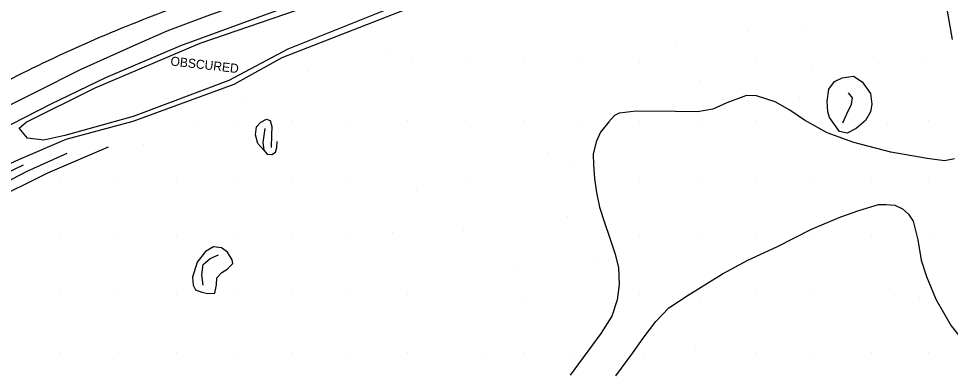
# Model space of a CAD drawing. Extents: x 524772 to 528246, y 273285 to 283088.
# Drawn here: x 526707.5 to 526864.4, y 277185.1 to 277244.2 of the extents above; entities that cross this region are included whole.
import ezdxf

# ---------------------------------------------------------------- set-up
doc = ezdxf.new("R2010")
doc.units = 0
for name, color, linetype in [('Exist Roads EOP', 7, 'Continuous'), ('PH Exist DTM Breakline', 7, 'Continuous'), ('PH Exist DTM Obscure Area', 7, 'Continuous'), ('PH Exist DTM Obscure Area Text', 7, 'Continuous'), ('PH Exist DTM Point', 7, 'Continuous')]:
    doc.layers.add(name, color=color, linetype=linetype)

msp = doc.modelspace()

# ---------------------------------------------------------------- linework, layer by layer
at = {"layer": 'Exist Roads EOP'}
for points in [[(526525.38, 277117.18), (526537.47, 277126.58), (526549.67, 277136.03), (526561.66, 277145.86), (526573.73, 277155.58), (526585.94, 277165.37), (526597.96, 277175.18), (526610, 277184.81), (526621.9, 277194.28), (526634.13, 277203.58), (526646.08, 277212.63), (526658.24, 277222.04), (526669.92, 277231.55), (526680.97, 277240.89), (526692.26, 277251.07), (526703.26, 277261.58), (526714.12, 277272.6), (526724.89, 277283.84)], [(526530.1, 277111.56), (526542.2, 277120.68), (526554.48, 277129.66), (526567.27, 277138.8), (526580.03, 277147.94), (526592.95, 277157.04), (526605.22, 277166), (526617.99, 277175.14), (526630.31, 277183.84), (526642.39, 277192.47), (526654.84, 277201.42), (526667.47, 277210.57), (526680.56, 277219.44), (526693.6, 277227.28), (526707.3, 277234.6), (526721.28, 277241.1), (526735.33, 277246.63), (526749.05, 277251.37), (526763.33, 277255.46)]]:
    msp.add_spline(points, degree=3, dxfattribs=at)
at = {"layer": 'PH Exist DTM Breakline'}
for points in [[(526763.16, 277254.94), (526770.89, 277255.73), (526781.75, 277257.24), (526792.41, 277258.33), (526805.01, 277259.77), (526814.77, 277261.06), (526820.49, 277262.09), (526831.77, 277264.5), (526839.43, 277266.1), (526844.64, 277267.15), (526846.81, 277267.46), (526848.71, 277267.21), (526850.47, 277266.69), (526852.49, 277265.75), (526854.47, 277264.73), (526856.33, 277263.31), (526858.04, 277261.63), (526859.43, 277260.28), (526861.08, 277258.13), (526862.05, 277255.93), (526863.07, 277250.3), (526864.72, 277240.67)], [(526847.95, 277264.75), (526844.32, 277264.46), (526838.89, 277263.84), (526832.99, 277262.77), (526819.99, 277260.54), (526807.41, 277258.41), (526799.95, 277257.02), (526790.72, 277255.24), (526777.17, 277252.42), (526771.43, 277250.94), (526751.2, 277245.63), (526734.74, 277239.62), (526722.1, 277234.23), (526712.9, 277229.79), (526692.94, 277219.54), (526680.47, 277212.08), (526671.94, 277206.38)], [(526668.44, 277207.44), (526674.33, 277211.13), (526682.73, 277216.49), (526694.76, 277223.83), (526701.36, 277227.29), (526710.42, 277231.84), (526718, 277235.67), (526727.3, 277239.84), (526732.51, 277242.1), (526739.25, 277244.63), (526749.19, 277248.25), (526758.54, 277251.05), (526765.41, 277252.59), (526775.09, 277254.44), (526784.56, 277255.93)], [(526789.24, 277250.35), (526781.49, 277248.42), (526774.73, 277246.51), (526751.8, 277237.58), (526743.72, 277233.09), (526726.74, 277226.86), (526715.41, 277223.85), (526707.44, 277220.38), (526700.02, 277217.03), (526690.01, 277212.14), (526686.82, 277210.4), (526682.59, 277208.58)], [(526845.76, 277225.15), (526844.09, 277227.52), (526843.81, 277228.48), (526843.66, 277230.28), (526843.93, 277232.32), (526844.93, 277233.61), (526846.2, 277234.21), (526848.11, 277234.47), (526849.57, 277233.56), (526850.95, 277231.57), (526851.2, 277229.8), (526850.97, 277228.46), (526850.12, 277227.01), (526848.54, 277225.69), (526847.02, 277224.91), (526845.76, 277225.15)], [(526865.13, 277220.56), (526863.41, 277220.24), (526860.54, 277220.61), (526854.39, 277221.7), (526848.17, 277223.32), (526843.66, 277224.97), (526839.83, 277227.11), (526837.39, 277228.78), (526834.9, 277230.19), (526831.77, 277231.19), (526830.07, 277231.24), (526826.75, 277230.03), (526824.39, 277228.93), (526821.83, 277228.47), (526818.1, 277228.55), (526811.48, 277228.58), (526808.66, 277228.29), (526807.86, 277227.87), (526806.9, 277226.78), (526805.51, 277225.09), (526804.75, 277223.45), (526804.23, 277221.34), (526804.31, 277219.56), (526804.48, 277217.28), (526804.82, 277214.9), (526805.34, 277212.43), (526806.24, 277209.7), (526806.98, 277207.37), (526807.91, 277204.67), (526808.5, 277202.3), (526808.63, 277199.41), (526808.28, 277196.85), (526807.39, 277194.1), (526805.57, 277191.17), (526800.36, 277184.16)], [(526846.3, 277226.64), (526847.21, 277228.67), (526847.76, 277229.72), (526847.94, 277230.87), (526847.25, 277231.7)], [(526748.96, 277225.69), (526748.63, 277223.3), (526748.76, 277222.01), (526747.79, 277223.18), (526747.35, 277224.63), (526747.52, 277225.96), (526748.26, 277226.73), (526749.21, 277227.26), (526749.83, 277227.01), (526750.15, 277226.04), (526750.09, 277224.61), (526750.03, 277222.46)], [(526748.76, 277222.01), (526749.33, 277221.37), (526750.15, 277221.29), (526750.76, 277221.71), (526750.95, 277222.51), (526751.05, 277223.49)], [(526666.98, 277193.82), (526672.99, 277197.85), (526680.2, 277202), (526686, 277205.39), (526689.44, 277207.33), (526692.18, 277209.1), (526694.86, 277210.75), (526697.53, 277212.3), (526700.33, 277213.76), (526703.33, 277215.46), (526706.45, 277217.2), (526708.93, 277218.52), (526712.27, 277220), (526715.64, 277221.54)], [(526722.58, 277222.53), (526712.35, 277218.16), (526702.59, 277213.31), (526695.98, 277209.65), (526688.44, 277205.32), (526683.34, 277202.17), (526672.12, 277194.36)], [(526664.98, 277195), (526680.6, 277204.65), (526686.38, 277207.77), (526693.81, 277211.96), (526701.97, 277216.51), (526708.31, 277219.56)], [(526808.07, 277184.04), (526810.91, 277187.9), (526812.65, 277190.36), (526814.79, 277193.21), (526817.02, 277195.48), (526820.28, 277197.6), (526826.02, 277201.2), (526830.33, 277203.52), (526835.22, 277205.77), (526841.03, 277208.72), (526845.99, 277210.81), (526849.01, 277211.86), (526852.3, 277212.88), (526853.62, 277212.86), (526855.06, 277212.76)], [(526855.06, 277212.76), (526856.34, 277212.18), (526857.4, 277211.26), (526858.14, 277210.06), (526858.93, 277206.93), (526859.52, 277203.5), (526860.43, 277200.78), (526861.96, 277196.97), (526864.54, 277192.44), (526867.83, 277188.37), (526869.48, 277186.49), (526870.82, 277184.15), (526871.02, 277181.99), (526870.94, 277180.29), (526874.53, 277179.12), (526877.73, 277178.28), (526879.55, 277178.02), (526882.35, 277177.75), (526884.99, 277178.27), (526885.43, 277181.95), (526887.82, 277180.97), (526889.8, 277181.4)], [(526740.54, 277197.97), (526740.81, 277199.36), (526740.89, 277200.53), (526741.68, 277201.46), (526742.63, 277201.99), (526743.55, 277202.93), (526743.45, 277203.58), (526742.64, 277204.84), (526741.67, 277205.61), (526740.33, 277205.78), (526738.93, 277204.99), (526737.54, 277203.16), (526736.76, 277200.66), (526736.9, 277199.3), (526737.29, 277198.5), (526738.36, 277198.11), (526739.3, 277197.91), (526740.54, 277197.97)], [(526738.55, 277199.29), (526738.35, 277201.02), (526738.58, 277202.76), (526739.72, 277203.79), (526741.17, 277204.42)]]:
    msp.add_lwpolyline(points, dxfattribs=at)
at = {"layer": 'PH Exist DTM Obscure Area'}
msp.add_lwpolyline([(526711.72, 277223.69), (526708.95, 277224.03), (526707.59, 277225.75), (526708.72, 277226.76), (526720.39, 277232.55), (526738.06, 277240.03), (526754.43, 277245.66), (526772.43, 277250.27), (526773.97, 277249.5), (526773.58, 277247.99), (526771.08, 277246.33), (526752.84, 277239.02), (526742.88, 277233.74), (526726.77, 277227.71), (526715.27, 277224.51), (526711.72, 277223.69)], dxfattribs=at)
at = {"layer": 'PH Exist DTM Point'}
for p, q in [((526830.38, 277241.94), (526830.38, 277241.94)), ((526840.01, 277242.96), (526840.01, 277242.96)), ((526818.3, 277240.08), (526818.3, 277240.08)), ((526769.37, 277238.15), (526769.37, 277238.15)), ((526859.71, 277236.99), (526859.71, 277236.99)), ((526773.73, 277236.71), (526773.73, 277236.71)), ((526782.8, 277236.82), (526782.8, 277236.82)), ((526792.55, 277236.82), (526792.55, 277236.82)), ((526802.3, 277236.82), (526802.3, 277236.82)), ((526812.06, 277236.82), (526812.06, 277236.82)), ((526831.56, 277236.82), (526831.56, 277236.82)), ((526841.2, 277236.02), (526841.2, 277236.02)), ((526852.3, 277236.68), (526852.3, 277236.68)), ((526756.32, 277235.29), (526756.32, 277235.29)), ((526822.15, 277233.81), (526822.15, 277233.81)), ((526745.23, 277230.95), (526745.23, 277230.95)), ((526838.96, 277230.83), (526838.96, 277230.83)), ((526737.67, 277225.99), (526737.67, 277225.99)), ((526743.78, 277227.06), (526743.78, 277227.06)), ((526753.53, 277227.06), (526753.53, 277227.06)), ((526763.29, 277227.06), (526763.29, 277227.06)), ((526773.04, 277227.06), (526773.04, 277227.06)), ((526782.78, 277227.08), (526782.78, 277227.08)), ((526792.55, 277227.06), (526792.55, 277227.06)), ((526802.3, 277227.06), (526802.3, 277227.06)), ((526812.08, 277226.93), (526812.08, 277226.93)), ((526821.85, 277226.79), (526821.85, 277226.79)), ((526831.56, 277227.06), (526831.56, 277227.06)), ((526853.81, 277226.35), (526853.81, 277226.35)), ((526860.8, 277227.07), (526860.8, 277227.07)), ((526728.5, 277223.05), (526728.5, 277223.05)), ((526796.51, 277221.58), (526796.51, 277221.58)), ((526801.04, 277219.78), (526801.04, 277219.78)), ((526714.52, 277217.31), (526714.52, 277217.31)), ((526724.27, 277217.31), (526724.27, 277217.31)), ((526734.03, 277217.31), (526734.03, 277217.31)), ((526743.79, 277217.34), (526743.79, 277217.34)), ((526753.53, 277217.31), (526753.53, 277217.31)), ((526763.29, 277217.31), (526763.29, 277217.31)), ((526782.8, 277217.31), (526782.8, 277217.31)), ((526812.06, 277217.31), (526812.06, 277217.31)), ((526821.81, 277217.31), (526821.81, 277217.31)), ((526831.56, 277217.31), (526831.56, 277217.31)), ((526841.32, 277217.31), (526841.32, 277217.31)), ((526851.07, 277217.31), (526851.07, 277217.31)), ((526860.82, 277217.31), (526860.82, 277217.31)), ((526774.45, 277215.25), (526774.45, 277215.25)), ((526799.93, 277210.81), (526799.93, 277210.81)), ((526714.52, 277207.55), (526714.52, 277207.55)), ((526724.27, 277207.55), (526724.27, 277207.55)), ((526734.03, 277207.55), (526734.03, 277207.55)), ((526744.56, 277208.08), (526744.56, 277208.08)), ((526753.53, 277207.55), (526753.53, 277207.55)), ((526763.29, 277207.55), (526763.29, 277207.55)), ((526770.52, 277208.18), (526770.52, 277208.18)), ((526782.36, 277208.48), (526782.36, 277208.48)), ((526812.05, 277207.5), (526812.05, 277207.5)), ((526821.81, 277207.55), (526821.81, 277207.55)), ((526831.56, 277207.55), (526831.56, 277207.55)), ((526851.07, 277207.55), (526851.07, 277207.55)), ((526861.1, 277207.59), (526861.1, 277207.59)), ((526841.53, 277207.09), (526841.53, 277207.09)), ((526804.93, 277203.48), (526804.93, 277203.48)), ((526791.54, 277202.26), (526791.54, 277202.26)), ((526714.52, 277197.8), (526714.52, 277197.8)), ((526724.27, 277197.8), (526724.27, 277197.8)), ((526734.03, 277197.8), (526734.03, 277197.8)), ((526743.78, 277197.8), (526743.78, 277197.8)), ((526753.53, 277197.8), (526753.53, 277197.8)), ((526763.29, 277197.8), (526763.29, 277197.8)), ((526812.06, 277197.8), (526812.06, 277197.8)), ((526831.56, 277197.8), (526831.56, 277197.8)), ((526841.32, 277197.8), (526841.32, 277197.8)), ((526854.2, 277198.77), (526854.2, 277198.77)), ((526773.05, 277197.66), (526773.05, 277197.66)), ((526792.87, 277196.46), (526792.87, 277196.46)), ((526822.26, 277196.82), (526822.26, 277196.82)), ((526859.21, 277197.29), (526859.21, 277197.29)), ((526821.47, 277189.02), (526821.47, 277189.02)), ((526714.52, 277188.05), (526714.52, 277188.05)), ((526724.27, 277188.05), (526724.27, 277188.05)), ((526734.03, 277188.05), (526734.03, 277188.05)), ((526743.78, 277188.05), (526743.78, 277188.05)), ((526753.53, 277188.05), (526753.53, 277188.05)), ((526763.29, 277188.05), (526763.29, 277188.05)), ((526773.04, 277188.05), (526773.04, 277188.05)), ((526785.65, 277188.05), (526785.65, 277188.05)), ((526792.55, 277188.05), (526792.55, 277188.05)), ((526800.33, 277187.41), (526800.33, 277187.41)), ((526812.8, 277187.01), (526812.8, 277187.01)), ((526831.56, 277188.05), (526831.56, 277188.05)), ((526841.32, 277188.05), (526841.32, 277188.05)), ((526851.07, 277188.05), (526851.07, 277188.05)), ((526860.82, 277188.05), (526860.82, 277188.05))]:
    msp.add_line(p, q, dxfattribs=at)

# ---------------------------------------------------------------- texts
at = {"layer": 'PH Exist DTM Obscure Area Text'}
msp.add_text('OBSCURED', height=1.524, rotation=353.4693, dxfattribs=at).set_placement((526732.99, 277236.31))

doc.saveas('drawing.dxf')
